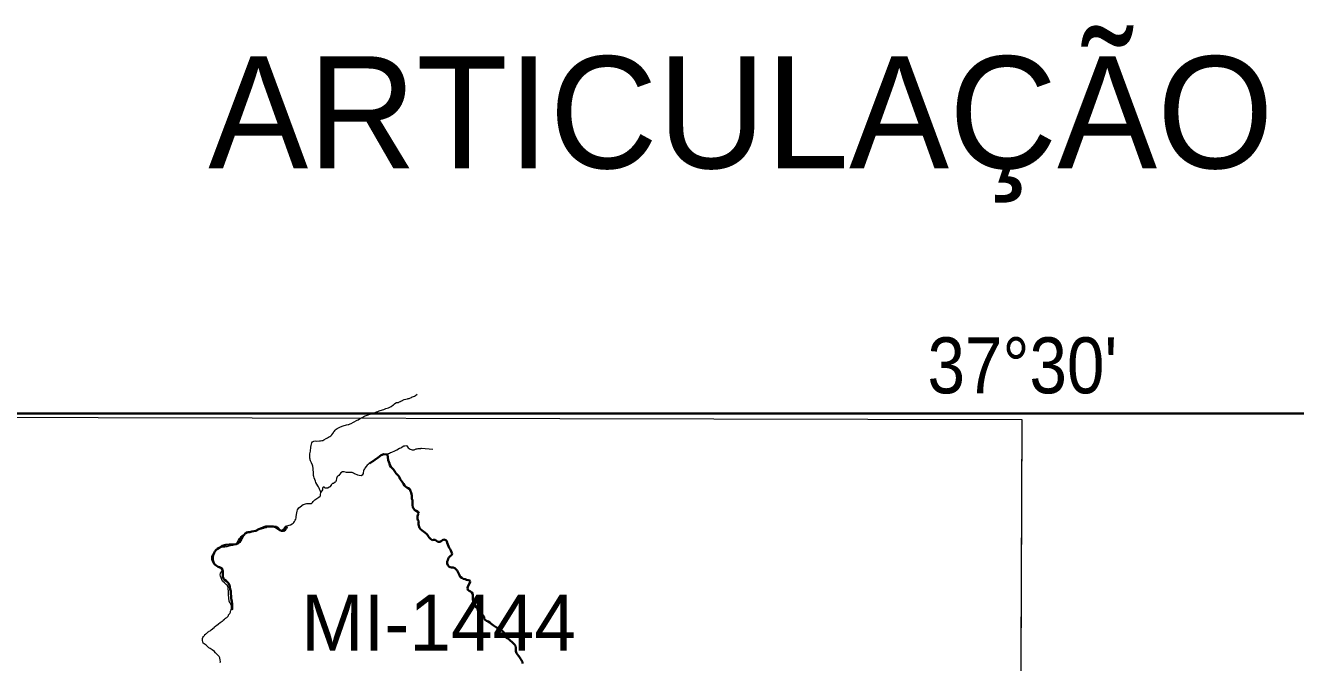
# Model space of a CAD drawing. Extents: x 553962 to 842807, y 8883888 to 9032388.
# Drawn here: x 587759 to 599099, y 8922544 to 8928234 of the extents above; entities that cross this region are included whole.
import ezdxf
from ezdxf.enums import TextEntityAlignment as Align

# ---------------------------------------------------------------- set-up
doc = ezdxf.new("R2010")
doc.units = 0
doc.header["$LTSCALE"] = 200
doc.linetypes.add('LONG_DASH_SHORT_DASH', pattern=[9.9, 6, -1.2, 1.5, -1.2])
doc.layers.add('6', color=7, linetype='Continuous', lineweight=13)

msp = doc.modelspace()

# ---------------------------------------------------------------- linework, layer by layer
at = {"layer": '6'}
for points in [[(590344.7, 8924524.1), (590346.1, 8924523.9), (590358, 8924520.2), (590383.2, 8924523.4), (590393.5, 8924524), (590404.1, 8924526.7), (590414.4, 8924528.6), (590424.7, 8924532.6), (590445.3, 8924544.2), (590455.6, 8924551.2), (590465.9, 8924557), (590475.9, 8924563.2), (590484.8, 8924569.5), (590494.8, 8924578.4), (590504.2, 8924588.4), (590517, 8924609.5), (590517.1, 8924611), (590524.6, 8924619.7), (590534, 8924627.8), (590543.3, 8924634.2), (590554.6, 8924640.6), (590565.1, 8924647.2), (590585.7, 8924656.2), (590595.8, 8924658.8), (590606, 8924660.2), (590616.3, 8924664), (590626.7, 8924667.2), (590639.5, 8924669.1), (590642.4, 8924669.9), (590647.3, 8924670.5), (590657.6, 8924675), (590667.6, 8924678.8), (590688.5, 8924691.7), (590719.6, 8924707.4), (590729.6, 8924713.1), (590749.9, 8924725.7), (590758.9, 8924730.8), (590770.5, 8924736.7), (590781.1, 8924741.4), (590792, 8924748.1), (590801.7, 8924751.7), (590820, 8924755.7), (590820.5, 8924756.1), (590821.9, 8924758.3), (590825.7, 8924760.6), (590832.6, 8924762.1), (590837.2, 8924763.8), (590843.2, 8924768), (590853.2, 8924770.5), (590864.6, 8924772.2), (590873.8, 8924775), (590883, 8924778.7), (590894.4, 8924783.6), (590904.4, 8924787.2), (590916.9, 8924790.8), (590946.9, 8924800.3), (590957.5, 8924804.8), (590977.5, 8924812.4), (591000.1, 8924819.7), (591023.1, 8924830.1), (591026.5, 8924831.2), (591031.1, 8924835.4), (591044.3, 8924845.6), (591048.9, 8924850.1), (591053.2, 8924853.7), (591065.5, 8924862.8), (591073.3, 8924865.4), (591078.4, 8924865.6), (591082.8, 8924866), (591088.7, 8924867.5), (591094.1, 8924870.2), (591105.1, 8924874.4), (591108, 8924875.9), (591112, 8924879.1), (591116.6, 8924880.1), (591120.9, 8924882.9), (591124.8, 8924885), (591128.7, 8924888.2), (591133.8, 8924890.1), (591139, 8924892.5), (591169.3, 8924900.3), (591175.2, 8924901.1), (591185.6, 8924903.8), (591196.1, 8924907.8), (591205.7, 8924912.7), (591211.1, 8924915.9), (591216, 8924918.4), (591231.2, 8924922.4), (591232.2, 8924923.5), (591240.4, 8924928.8), (591244.5, 8924932.2), (591253.5, 8924937.3), (591256.3, 8924939.6)], [(596655.5, 8924715.8), (596593.3, 8909930.3), (596531.7, 8896026.7)], [(590992.5, 8924408.9), (590998.2, 8924407.9), (591001.7, 8924410.6), (591009.4, 8924414.9), (591019.6, 8924420.2), (591029, 8924424.2), (591055.7, 8924433.9), (591064.4, 8924438.2), (591073.7, 8924444.1), (591099.9, 8924459.1), (591109.4, 8924462.7), (591118.2, 8924467), (591130.4, 8924475.9), (591134.9, 8924476.9), (591136.3, 8924478.6), (591137.1, 8924478.9), (591145.2, 8924480.7), (591162.1, 8924481.3), (591169.8, 8924470.2), (591176.4, 8924462.5), (591185.8, 8924454.4), (591193.6, 8924448.8), (591202.3, 8924445.7), (591211.4, 8924443.2), (591228.4, 8924443.3), (591248, 8924451.7), (591256.5, 8924453.6), (591265.2, 8924454.9), (591274.8, 8924454.9), (591289.2, 8924456.1), (591290.2, 8924456.7), (591292.7, 8924458.8), (591295.8, 8924459), (591395.2, 8924449.5)], [(590397.2, 8924064.7), (590397.2, 8924064.7), (590389.6, 8924081.3), (590384.3, 8924092), (590380.2, 8924102.3), (590374.6, 8924112.4), (590369.9, 8924122.8), (590352.7, 8924153), (590347.6, 8924162.9), (590342.2, 8924179.5), (590338.2, 8924194.3), (590335, 8924204.5), (590332.3, 8924215.2), (590331, 8924235.1), (590330.9, 8924245.8), (590328.3, 8924265.8), (590328.2, 8924276.7), (590325.6, 8924296.8), (590322, 8924307.9), (590312.8, 8924329.1), (590304.5, 8924346.2)], [(590992.5, 8924402.1), (590990.2, 8924402.6), (590973.7, 8924404.6), (590952.7, 8924402.9), (590942.3, 8924398.3), (590932.8, 8924393.6), (590923, 8924387.5), (590914.7, 8924381.7), (590891.1, 8924363.9), (590882.9, 8924358.3), (590876.5, 8924353.5), (590862.7, 8924340.9), (590854.6, 8924335.8), (590835.3, 8924325.4), (590826.3, 8924319.7), (590818, 8924313.8), (590811.3, 8924307.8), (590800.4, 8924295.7), (590789.2, 8924281.4), (590785.1, 8924274.4), (590781.3, 8924266.7), (590778.8, 8924256.9), (590775.1, 8924237.1), (590773.8, 8924233.8), (590764.3, 8924217.2), (590758, 8924212.3), (590755.1, 8924211.9), (590738, 8924216), (590727.2, 8924217.6), (590721.5, 8924220.6), (590706.8, 8924226.4), (590696.7, 8924230.7), (590688.6, 8924236.5), (590677, 8924242.1), (590646.8, 8924242.2), (590635.5, 8924241.6), (590625.2, 8924242.9), (590604.8, 8924247.7), (590590, 8924247.6), (590588.5, 8924247.4), (590574.8, 8924237.1), (590556.4, 8924214), (590548.1, 8924207.6), (590540.8, 8924200.3), (590539, 8924198), (590538.7, 8924197.1), (590538.5, 8924194.4), (590536.1, 8924190.7), (590534.2, 8924168.1), (590532.4, 8924165.1), (590530.3, 8924164.5), (590527.7, 8924157.9), (590523.1, 8924155.6), (590510, 8924144.5), (590501.7, 8924142.9), (590490.8, 8924134.1), (590489.8, 8924130.3), (590488.1, 8924129.4), (590477.2, 8924114.8), (590471.2, 8924109.6), (590459.3, 8924102), (590457.6, 8924101.6), (590440.8, 8924101.2), (590440.2, 8924101.4), (590439, 8924102.9), (590436.2, 8924103), (590432, 8924105.7), (590431, 8924107.3), (590427.5, 8924108.1), (590425.4, 8924110.3), (590416, 8924109.2), (590415.1, 8924105.6), (590413, 8924103.7), (590412.7, 8924103.2), (590411.1, 8924087.9), (590397.2, 8924064.7)], [(589516.7, 8923577.1), (589538.1, 8923578.1), (589548.8, 8923580.6), (589560.2, 8923581.6), (589569.4, 8923583.3), (589579.4, 8923585.8), (589590.3, 8923590.3), (589607, 8923592.8), (589610.7, 8923593), (589621.2, 8923596.4), (589631.2, 8923602.7), (589640.6, 8923608.9), (589649, 8923617.2), (589661.2, 8923635.9), (589671.7, 8923653.4), (589678, 8923660.6), (589684.5, 8923668.9), (589692.2, 8923676.6), (589712.7, 8923690.4), (589723, 8923695), (589763.3, 8923710.2), (589780, 8923711.5), (589784.3, 8923712.3), (589805.5, 8923720.1), (589825.2, 8923726.3), (589835.1, 8923728.3), (589846, 8923731.7), (589856.3, 8923735.5), (589866.9, 8923738.3), (589887, 8923745.7), (589899.2, 8923749), (589907.8, 8923751.8), (589918.2, 8923755.6), (589928.5, 8923757.5), (589945.5, 8923758.9), (589949.4, 8923759.5), (589962.9, 8923759.5), (589969.1, 8923759), (589971.3, 8923758.2), (589991.2, 8923749.3), (590013.6, 8923734.5), (590015.6, 8923732.4), (590018, 8923732.1), (590018.8, 8923730), (590019.5, 8923729.4), (590040.4, 8923724.8), (590041.7, 8923725), (590051, 8923729.2), (590060.6, 8923735), (590068.8, 8923742.4), (590083.2, 8923761.2), (590093.2, 8923765), (590103.7, 8923768.5), (590113.7, 8923772.2), (590124.3, 8923774.9), (590141.8, 8923783.6), (590149.8, 8923790.2), (590155.1, 8923795.5), (590162.2, 8923804.2), (590168.8, 8923815.7), (590172.5, 8923825.7), (590175.5, 8923835.3), (590175.7, 8923846.6), (590178.2, 8923866.7), (590185.8, 8923897.6), (590188.8, 8923907.7), (590194.8, 8923917.5), (590200.8, 8923925.8), (590210.7, 8923934.5), (590238.8, 8923955.5), (590271.9, 8923963.9), (590292.3, 8923963.9), (590306.4, 8923963.4), (590312, 8923965.1), (590320.8, 8923973.6), (590326.7, 8923981.9), (590333.3, 8923989.3), (590341.6, 8923996.5), (590361.1, 8924009.5), (590378.2, 8924022.2), (590391.5, 8924031), (590393.5, 8924037.1), (590394.6, 8924044), (590393.9, 8924046.5), (590397.1, 8924063), (590397.2, 8924064.7)], [(589500.8, 8923316.4), (589497.4, 8923327.4), (589499.4, 8923339.3), (589501, 8923341.2), (589502, 8923343.6), (589509.3, 8923353.2), (589510.9, 8923357.4), (589513.7, 8923360.2), (589514.2, 8923361.5), (589515.2, 8923369.6), (589514, 8923378.3), (589507.6, 8923392.2), (589502.1, 8923396.1), (589495.2, 8923398.9), (589475, 8923406.2), (589463.6, 8923412.9), (589453.8, 8923420.2), (589443.6, 8923429), (589435.7, 8923436.2), (589428.2, 8923446.1), (589425.5, 8923454), (589424.1, 8923463.2), (589422.2, 8923489.5), (589423.2, 8923490.8), (589430, 8923506.7), (589434.9, 8923512.9), (589439.6, 8923519.5), (589449.5, 8923531.9), (589454.7, 8923539.7), (589458.4, 8923543.1), (589459.4, 8923547.2), (589461.9, 8923548.3), (589474.8, 8923558.2), (589516.7, 8923577.1)], [(589338.9, 8922741.2), (589338.8, 8922746.3), (589340.7, 8922759.1), (589343.2, 8922767.2), (589348.9, 8922777), (589356.6, 8922785.8), (589359.8, 8922791.1), (589362.2, 8922793.4), (589369.6, 8922799), (589373.1, 8922802.4), (589379.9, 8922807.3), (589387.7, 8922815.1), (589392.1, 8922817.7), (589396.6, 8922820.9), (589400.9, 8922823.2), (589407.8, 8922827.8), (589410.8, 8922830), (589417.8, 8922837), (589427.9, 8922845.1), (589432.4, 8922849.7), (589443.9, 8922858.7), (589448.7, 8922863.3), (589478.5, 8922888.2), (589483.8, 8922891.4), (589496.7, 8922900.7), (589507.2, 8922907.3), (589516.2, 8922913.7), (589520.7, 8922917.5), (589525.2, 8922921.8), (589536.8, 8922931.1), (589539.5, 8922934.5), (589544.3, 8922939.2), (589547.5, 8922941.3), (589550.8, 8922944.3), (589556, 8922947.7), (589559.1, 8922950.1), (589567.9, 8922959.8), (589570.8, 8922963.9), (589573.4, 8922969), (589575.7, 8922972.4), (589584.2, 8922983.5), (589586.3, 8922987.3), (589589.4, 8922994.1), (589591.3, 8923001.8), (589593.9, 8923009.7), (589595.6, 8923016.5), (589598.2, 8923032.3), (589598.3, 8923038.9), (589598.8, 8923046), (589598.1, 8923052), (589594.3, 8923064.6), (589586.6, 8923077.4), (589581.5, 8923087.3), (589579.4, 8923090.2), (589576.8, 8923096.9), (589574.8, 8923115.9), (589574.7, 8923128.7), (589572.2, 8923141.7), (589572.1, 8923166.5), (589571.4, 8923174.8), (589572, 8923181.2), (589572, 8923187.4), (589570.7, 8923193.9), (589570.6, 8923200.3), (589569.4, 8923206.9), (589568.7, 8923215.2), (589566.8, 8923223.1), (589565.5, 8923223.8), (589565.2, 8923226.3), (589560, 8923234), (589552.3, 8923240.3), (589538.4, 8923254.4), (589519, 8923270.7), (589512.2, 8923285.9)], [(589512.2, 8923285.9), (589505.5, 8923301.3), (589500.8, 8923316.4)], [(589498.8, 8922543.7), (589499.9, 8922553.6), (589498.6, 8922564.5), (589495.3, 8922585.8), (589493.7, 8922587.8), (589487.6, 8922597.4), (589480, 8922606.1), (589458, 8922627), (589457.7, 8922628.5), (589456.1, 8922628.9), (589455.7, 8922631.9), (589451.9, 8922634.7), (589447.8, 8922642.2), (589427.8, 8922657), (589418, 8922663.8), (589407.5, 8922670.3), (589398, 8922677.1), (589389.1, 8922685.1), (589376.8, 8922695.6), (589372.3, 8922698.8), (589371.6, 8922700.5), (589347.3, 8922716.4), (589346.4, 8922718.1), (589338.9, 8922741.2)]]:
    msp.add_lwpolyline(points, dxfattribs=at)
at = {"layer": '6', "lineweight": 35}
msp.add_lwpolyline([(574695.3, 8924769.6), (626625.7, 8924769.6), (626625.7, 8896026.7), (574695.3, 8896026.7)], close=True, dxfattribs=at)
at = {"layer": '6'}
msp.add_lwpolyline([(585656.3, 8924738.8), (596655.5, 8924715.8), (596639.8, 8920989.8), (585645.8, 8921027.3)], close=True, dxfattribs=at)
at = {"layer": '6', "linetype": 'LONG_DASH_SHORT_DASH', "lineweight": 35}
for points in [[(591402.7, 8923639.7), (591389.2, 8923638.7), (591375.1, 8923649.2), (591364.5, 8923660.2), (591355.4, 8923672.7), (591347.8, 8923684.2), (591338.7, 8923695.2), (591325.6, 8923706.7), (591312, 8923715.7), (591300.9, 8923724.2), (591287.3, 8923736.1), (591278.2, 8923748.7), (591268.1, 8923776.2), (591269, 8923791.8), (591271, 8923805.9), (591262.4, 8923816.9), (591258.8, 8923831.9), (591259.3, 8923848.5), (591263.2, 8923863.1), (591270.2, 8923876.2), (591263.1, 8923890.2), (591249, 8923899.2), (591235.9, 8923905.1), (591223.3, 8923918.6), (591218.8, 8923932.2), (591215.7, 8923949.2), (591215.6, 8923980.3), (591215, 8923993.9), (591208.4, 8924006.9), (591208.3, 8924035.1), (591207.3, 8924048.6), (591203.2, 8924062.6), (591196.1, 8924075.7), (591191.5, 8924091.7), (591177.4, 8924102.2), (591164.8, 8924107.7), (591152.8, 8924115.7), (591142.7, 8924126.2), (591133.1, 8924139.7), (591123.5, 8924157.2), (591105.3, 8924183.2), (591099.7, 8924195.8), (591092.1, 8924207.3), (591082, 8924219.3), (591070.4, 8924231.8), (591060.8, 8924243.8), (591054.8, 8924257.8), (591041.6, 8924270.3), (591021.5, 8924292.8), (591012.4, 8924307.9), (591008.8, 8924321.9), (590998.8, 8924350.2), (590992.5, 8924403.6), (590959.8, 8924405.2), (590935.8, 8924396.5), (590908.7, 8924376.5), (590878.4, 8924353.4), (590830.6, 8924322.3)], [(590095.4, 8923759.3), (590091.6, 8923755.2), (590086.2, 8923742.6), (590078.2, 8923729), (590063.1, 8923721.9), (590045.5, 8923720.3), (590031.9, 8923727.8), (590011.7, 8923748.3), (590000.2, 8923755.8), (589984.1, 8923756.7), (589970.5, 8923758.2), (589955.4, 8923759.1), (589906.1, 8923758.9), (589888.1, 8923754.3), (589876, 8923747.7), (589858, 8923740.1), (589842.9, 8923735.5), (589815.3, 8923721.4), (589779.6, 8923713.2), (589762.1, 8923709.6), (589748.5, 8923709), (589732.9, 8923704.4), (589720.4, 8923696.8), (589711.9, 8923686.3), (589703.9, 8923675.2), (589686.9, 8923648.5), (589679.9, 8923633.9), (589669.4, 8923618.8), (589654.3, 8923608.2), (589639.8, 8923602.6), (589624.2, 8923598), (589606.1, 8923597.4), (589577.5, 8923597.3), (589547.8, 8923595.2), (589516.7, 8923586.5), (589487.6, 8923569.3), (589474.1, 8923560.2), (589463, 8923552.1), (589450, 8923535.5), (589443, 8923523.4), (589434.5, 8923504.3), (589433.6, 8923489.7), (589432.1, 8923474.7), (589432.2, 8923458.6), (589438.8, 8923442), (589443.9, 8923427), (589454, 8923417.5), (589481.2, 8923399), (589495.2, 8923394.6), (589508.3, 8923387.6), (589517.5, 8923372.6), (589521, 8923358.5), (589521.1, 8923325.4), (589521.7, 8923309.8), (589526.8, 8923294.8), (589535.4, 8923281.8), (589550, 8923273.8)], [(591592.6, 8923388.5), (591579, 8923392.4), (591563.9, 8923394.4), (591549.9, 8923394.8), (591537.8, 8923401.8), (591529.7, 8923412.8), (591525.6, 8923429.9), (591525.1, 8923445.4), (591529, 8923458.5), (591534, 8923471.6), (591540.5, 8923483.7), (591551, 8923493.7), (591563, 8923503.3), (591569.5, 8923515.9), (591562.4, 8923528.9), (591555.8, 8923543.5), (591550.8, 8923557.5), (591542.2, 8923569.5), (591535.6, 8923584.1), (591531.5, 8923598.6), (591525.4, 8923613.6), (591521.4, 8923627.7), (591511.3, 8923637.2), (591495.7, 8923643.6), (591482.6, 8923636.6), (591471.1, 8923628), (591458.1, 8923620.9), (591442, 8923621.3), (591428.9, 8923629.8), (591417.8, 8923640.3), (591402.7, 8923639.7)], [(592179.5, 8922576.1), (592172.9, 8922589.1), (592160.3, 8922603.6), (592151.7, 8922615.6), (592144.1, 8922629.2), (592137.5, 8922646.7), (592137.4, 8922676.8), (592133.8, 8922692.4), (592126.2, 8922705.9), (592114.1, 8922717.9), (592078.8, 8922751.4), (592064.7, 8922758.4), (592052.6, 8922765.8), (592039.5, 8922776.8), (592035, 8922789.9), (592032.9, 8922803.4), (592027.8, 8922819), (592016.2, 8922828.9), (592004.6, 8922837.4), (591990, 8922845.9), (591964.4, 8922857.8), (591938.7, 8922876.3), (591925.1, 8922882.8), (591914, 8922892.8), (591903.9, 8922902.8), (591890.8, 8922911.8), (591876.2, 8922917.2), (591862.6, 8922925.2), (591855, 8922937.2), (591855, 8922953.8), (591844.4, 8922963.3), (591830.8, 8922966.7), (591826.7, 8922982.8), (591817.2, 8922992.8), (591804.6, 8922998.2), (591798.5, 8923010.8), (591793.9, 8923023.8), (591784.8, 8923036.3), (591777.7, 8923051.9), (591770.2, 8923063.9), (591763.6, 8923079.4), (591756.5, 8923094.9), (591752.9, 8923111.5), (591752.8, 8923140.6), (591752.2, 8923155.7), (591745.2, 8923169.2), (591733.1, 8923180.2), (591719.5, 8923184.7), (591707.4, 8923194.2), (591705.8, 8923209.2), (591709.3, 8923222.8), (591722.8, 8923248.9), (591729.2, 8923264), (591727.2, 8923277.6), (591712.1, 8923280), (591697, 8923284), (591684.4, 8923289.5), (591666.8, 8923292.9), (591654.2, 8923299.9), (591641.6, 8923310.4), (591633, 8923323.4), (591627.5, 8923337.9), (591612.8, 8923366), (591602.7, 8923378), (591592.6, 8923388.5)], [(589550, 8923273.8), (589562.6, 8923262.8), (589572.7, 8923252.8), (589580.3, 8923236.7), (589585.3, 8923220.2), (589588.4, 8923200.6), (589592.5, 8923183.1), (589592.6, 8923164), (589594.7, 8923132.3), (589596.3, 8923117.3), (589599.3, 8923103.2), (589600.9, 8923089.7), (589603.5, 8923071.6), (589604, 8923056.6), (589604.1, 8923041.5), (589603.6, 8923025.4), (589601.5, 8923015.4)], [(592195.7, 8922536), (592195.6, 8922551.6), (592179.5, 8922576.1)]]:
    msp.add_lwpolyline(points, dxfattribs=at)
at = {"layer": '6'}
msp.add_spline([(590304.5, 8924346.2), (590297.2, 8924376.4), (590301.6, 8924419.9), (590308.1, 8924468.9), (590323.3, 8924514.7), (590344.7, 8924524.1)], degree=3, dxfattribs=at)

# ---------------------------------------------------------------- texts
msp.add_text('ARTICULAÇÃO DAS CARTAS 1:100.000', height=1000, dxfattribs=at).set_placement((601765.5, 8926958.2), align=Align.CENTER)
at = {"layer": '6', "width": 0.9}
msp.add_text("37°30'", height=500, dxfattribs=at).set_placement((596659.7, 8924948.5), align=Align.CENTER)
at = {"layer": '6'}
msp.add_text('MI-1444', height=500, dxfattribs=at).set_placement((590221.3, 8922649.4))

doc.saveas('drawing.dxf')
